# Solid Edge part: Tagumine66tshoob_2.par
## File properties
Author: KULL
Template: Iso Metric Part.par
Last saved by: KULL
Revision: 10
Application: Solid Edge
Accuracy: 0,990
Face Style: Model Default
Fill Style: Normal
Coef. of Thermal Exp: 0.0
Thermal Conductivity: 0.0
Specific Heat: 0.0
Modulus of Elasticity: 0.0
Poisson's Ratio: 0.0
Yield Stress: 0.0
Ultimate Stress: 0.0
Elongation: 0.0
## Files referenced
..\..\Rover_ASM.asm
D:\Solid edge leong\Solid edge Sync practice\ROVER_Heiko_Kull_EKSAM\Poldid_pulgad\66tshoova_Tagumine_kinnituspolt.par
D:\Solid edge leong\Solid edge Sync practice\ROVER_Heiko_Kull_EKSAM\Raam\Chassy_1.par
D:\Solid edge leong\Solid edge Sync practice\ROVER_Heiko_Kull_EKSAM\Roolimise_jupid\frontsteering_1.par
QD:\Solid edge leong\Solid edge Sync practice\ROVER_Heiko_Kull_EKSAM\Rover_ASM.asm
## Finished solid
Body 1: sheet body, 1 face, 19 edges, 18 vertices.
  Faces by surface: plane 1
  Edges by curve: line 15, circle 4
Body 2: sheet body, 1 face, 1 edge, 0 vertices.
  Faces by surface: sphere 1
  Edges by curve: circle 1
Body 3: sheet body, 1 face, 2 edges, 0 vertices.
  Faces by surface: cylinder 1
  Edges by curve: circle 2
Body 4: solid body, 15 faces, 15 edges, 0 vertices.
  Faces by surface: cylinder 6, plane 6, torus 2, blend 1
  Edges by curve: circle 13, intersection 2
Bounding box of the edges (mm; curved faces can reach further): 381.642 x 71.851 x 13.899, from (-379.46, 40, 47.912) to (2.1818, 111.8511, 61.811).
Cylindrical faces by radius (mm): R2 x1, R2.5 x2, R2.5057 x1, R3 x2, R5 x1
Toroidal faces (ring radius, tube radius in mm): R4.6 r0.4 x2
Spherical faces by radius (mm): R4 x1
Planar faces by outward normal: +x 1, -x 1, oblique 4
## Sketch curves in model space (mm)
line (-332.46, 45, 56.811) -> (-332.46, 109.6693, 51.2645)
line (-342.46, 82.0712, 53.6315) -> (-342.46, 85.1575, 53.3668)
line (-342.46, 45, 56.811) -> (-342.46, 109.6693, 51.2645)
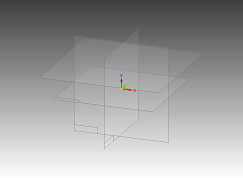
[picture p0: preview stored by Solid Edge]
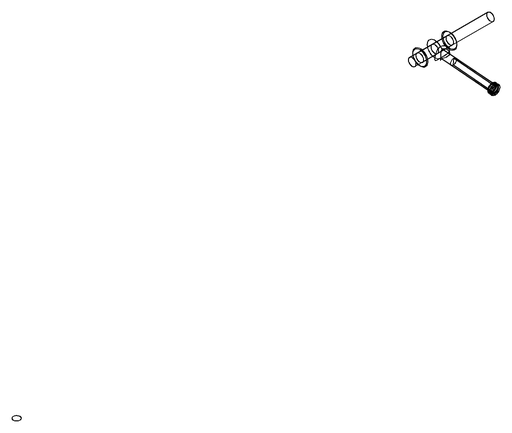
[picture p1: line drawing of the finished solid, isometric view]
